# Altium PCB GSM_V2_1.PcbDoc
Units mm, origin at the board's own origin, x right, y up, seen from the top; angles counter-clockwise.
Board outline 86 x 46.6 mm, 2 copper layers (Top Layer, Bottom Layer); 76 components, 54 nets, 270 pads, 34 vias.
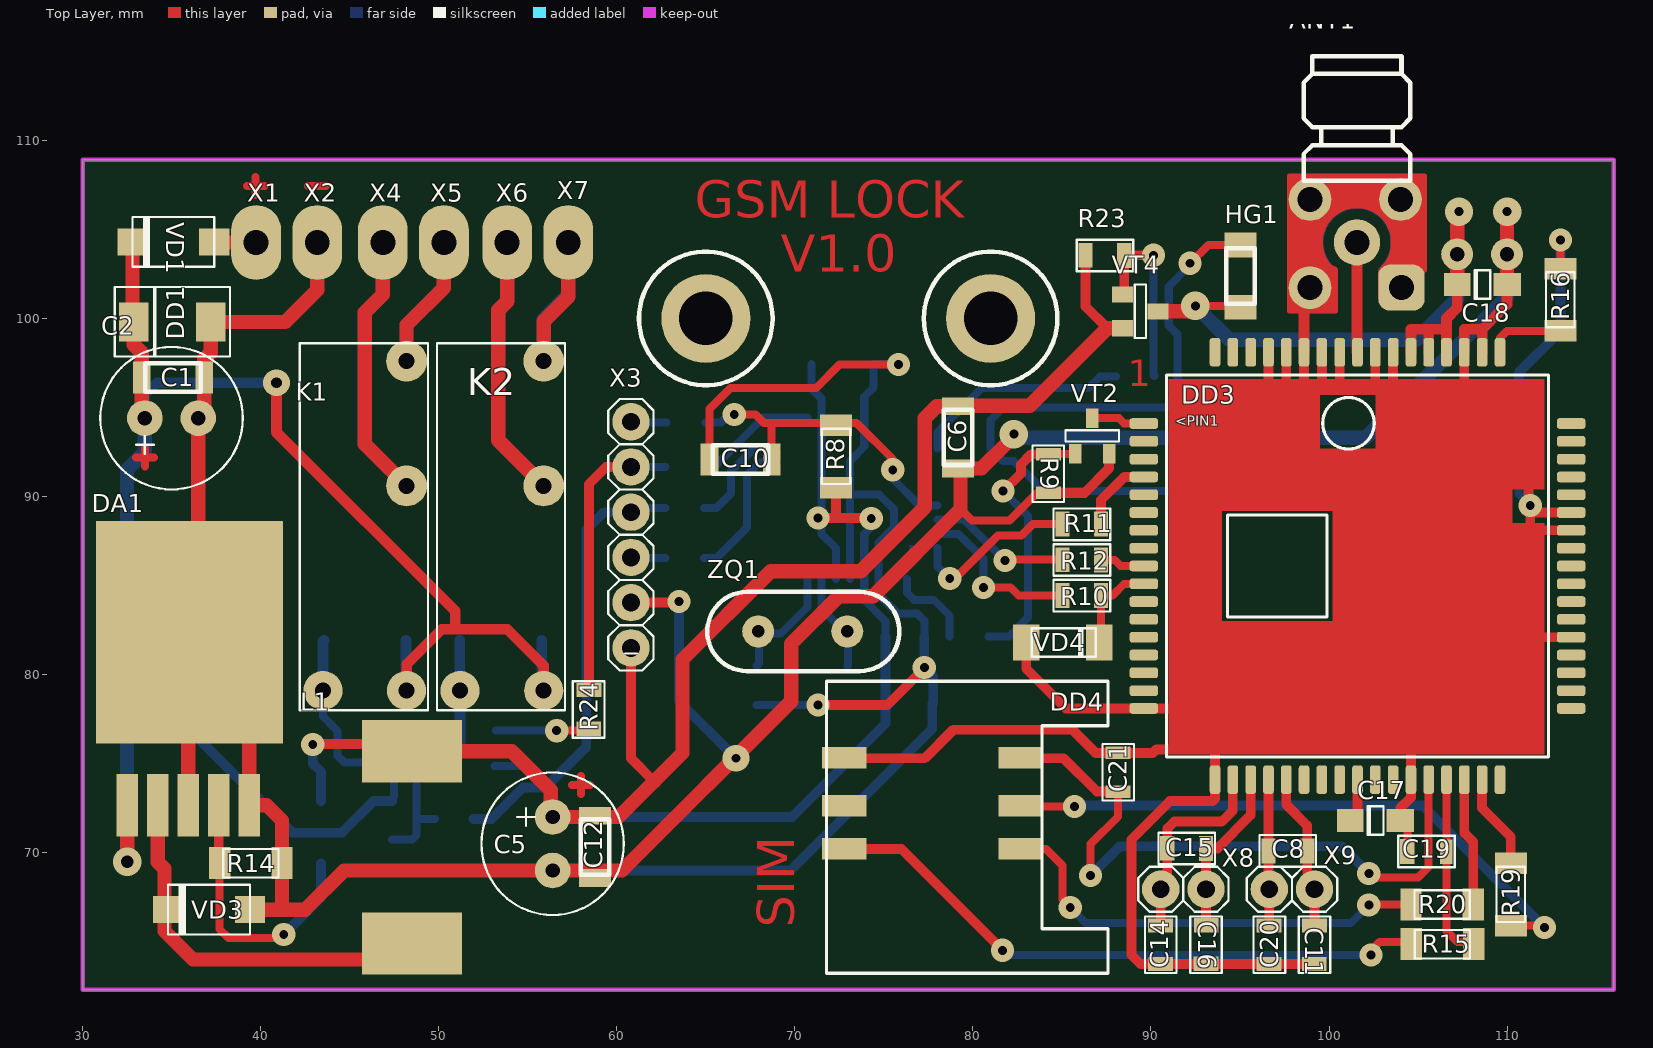
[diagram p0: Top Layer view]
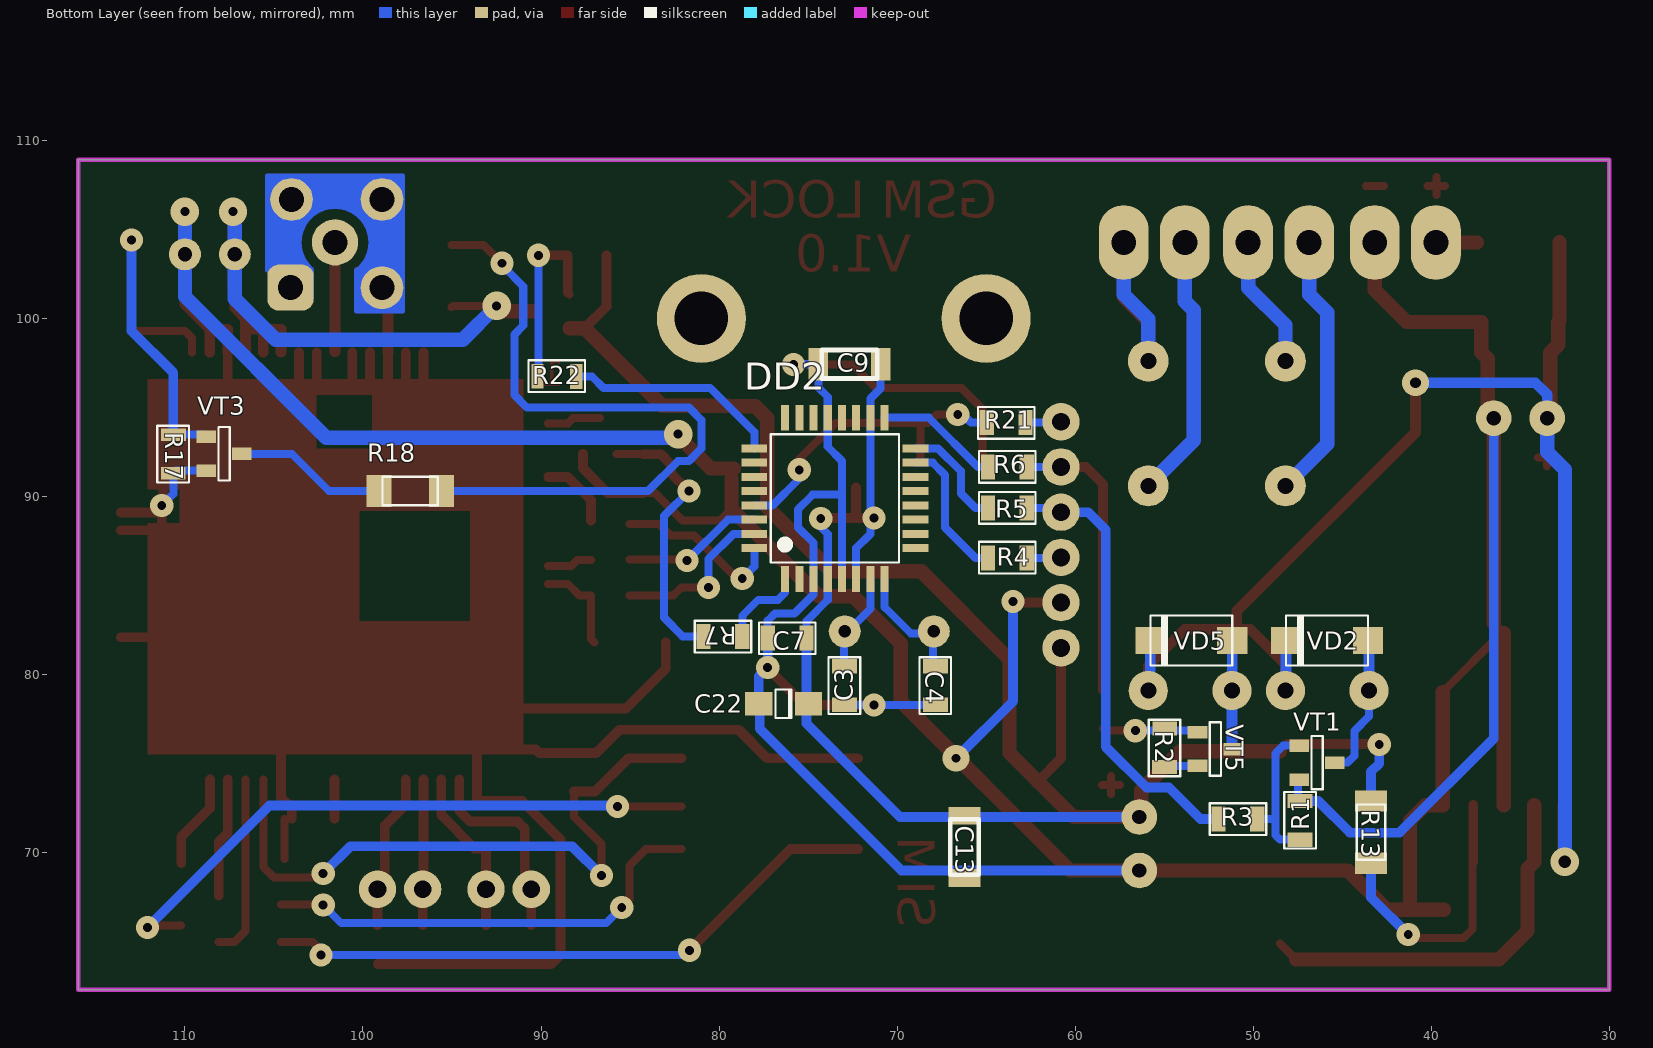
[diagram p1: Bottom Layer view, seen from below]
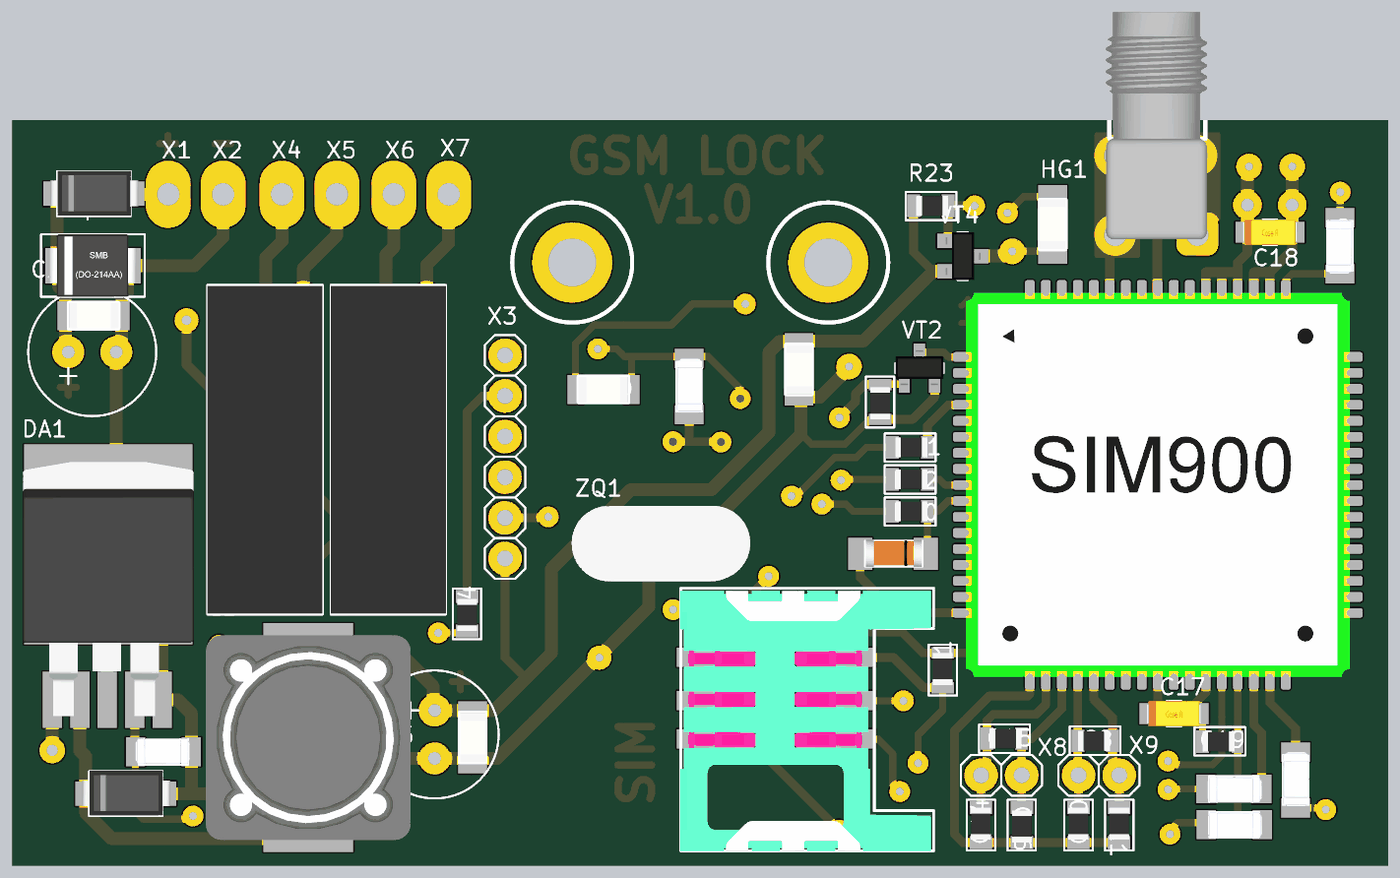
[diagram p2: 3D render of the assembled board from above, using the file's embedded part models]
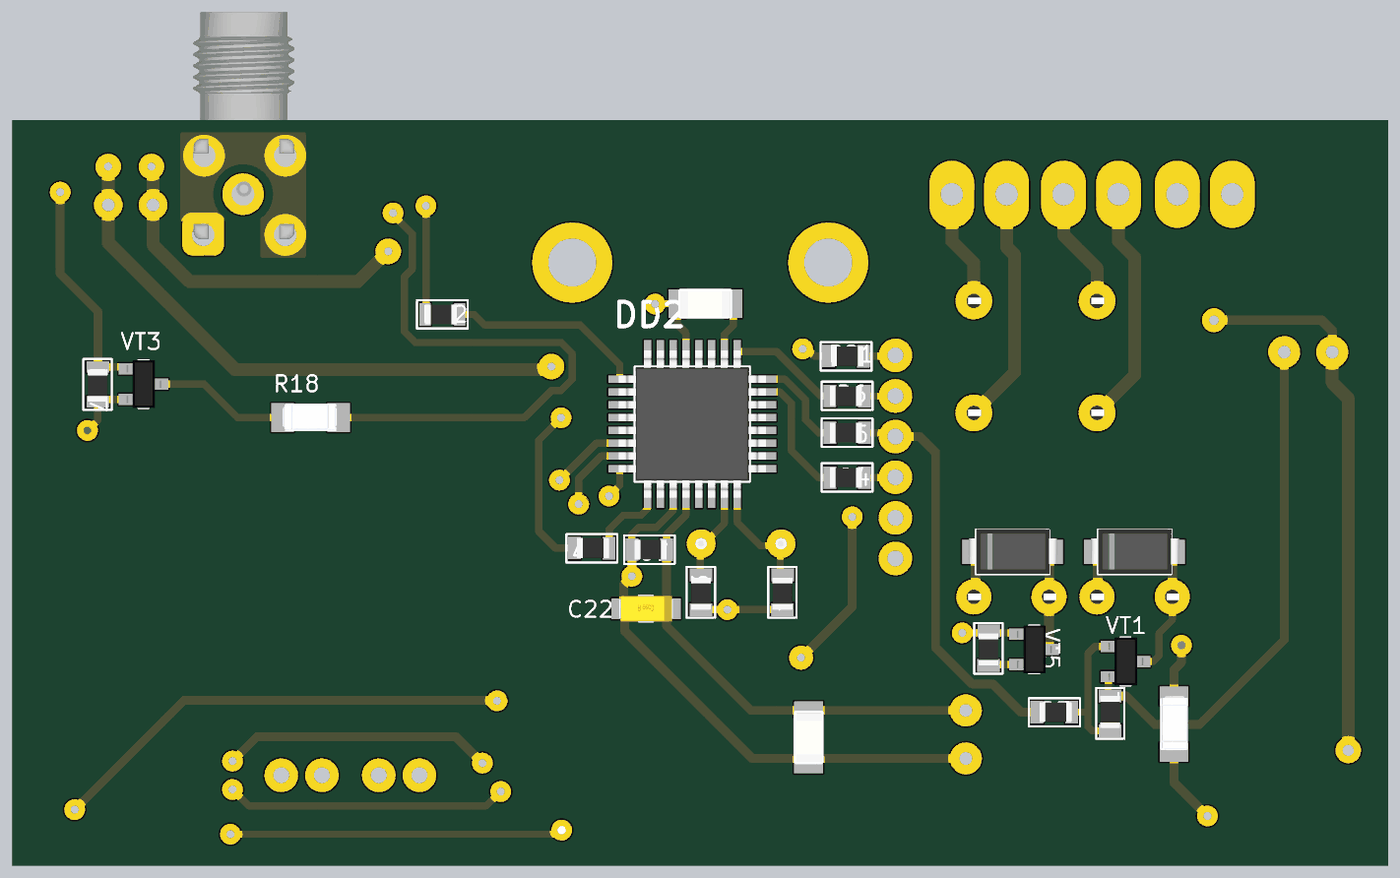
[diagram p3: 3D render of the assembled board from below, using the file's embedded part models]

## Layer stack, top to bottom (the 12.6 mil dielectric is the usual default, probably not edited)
Top Solder: solder mask 0.0102, Solder Resist, Dk 3.5
Top Layer: signal copper 0.0356
Dielectric 1: dielectric 0.32, FR-4, Dk 4.8
Bottom Layer: signal copper 0.0356
Bottom Solder: solder mask 0.0102, Solder Resist, Dk 3.5

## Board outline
30,62.3 116,62.3 116,108.9 30,108.9

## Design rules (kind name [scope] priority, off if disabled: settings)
Clearance [All] p1: gap=0.23
PolygonConnect [All] p1: connectstyle=Relief reliefconductorwidth=0.254 reliefentries=4 polygonreliefangle="90 Angle" airgapwidth=0.254
RoutingVias [All] p1: holewidth=0.711 width=1.27 viastyle="Through Hole" minholewidth=0.711 minwidth=1.27 maxholewidth=0.711 maxwidth=1.27
SMDNeckDown [All] p1: percent=100.000
SolderMaskExpansion [All] p1: expansion=0.102
Width [All] p1: maxlimit=0.8 minlimit=0.45 preferedwidth=0.6
29 further rules are at their usual default settings.

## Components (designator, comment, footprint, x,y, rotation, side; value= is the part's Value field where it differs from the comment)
ANT1 "ANT" ANTENNA 101.6,104.3 r0 top
C1 "100nF" 1206_CAP#1 33.2,97.3 r0 top
C2 "470uF" 3mm 36.5,94.4 r180 top
C3 "18" 0805#1 73.6,78.3 r90 bottom
C4 "18" 0805#1 68.5,78.3 r90 bottom
C5 "1000uF" 3mm 56.4,69 r90 top
C6 "100nF" 1206_CAP#1 79.8,95.2 r270 top
C7 "100nF" 0805#1 75.1,81.407 r0 bottom
C8 "10" 0805#1 96.6,70.739 r0 top
C9 "100nF" 1206_CAP#2 70.8,96.8 r0 bottom
C10 "100nF" 1206_CAP#1 68.834,91.44 r180 top
C11 "10" 0805#1 99.822,65.913 r270 top
C12 "100nF" 1206_CAP#1 59.4,72.2 r270 top
C13 "100nF" 1206_CAP#1 65.6,72.2 r270 bottom
C14 "10" 0805#1 91.186,65.913 r270 top
C15 "10" 0805#1 93.091,69.596 r180 top
C16 "10" 0805#1 92.456,63.754 r90 top
C17 "4.7uF" A 104.2,71.8 r180 top
C18 "10uF" A 110.2,101.9 r180 top
C19 "10" 0805#2 104.4,70.7 r0 top
C20 "10" 0805#1 97.282,65.913 r270 top
C21 "100nF" 0805#3 88.8,75.6 r270 top
C22 "10uF" A 77.978,78.359 r180 bottom
DA1 "LM2576S-ADJ" D2PAK-5 36,83.4 r270 top
DD1 "SMBJ15A" SMB(DO-214AA) 37.2,99.8 r180 top
DD2 "Atmega8A-AU" TQFP32 76.3,85.5 r90 bottom
DD3 "SIM900R" SIM900 89.6,98.1 r0 top
DD4 "SIM_card" 6393699-1 71.882,79.629 r0 top
HG1 "LED_3mm" 1206_CAP#3 94.4,100.5 r90 top
K1 "G5NB-1A-E" G5NB-1A-E 43.5,79.1 r90 top
K2 "G5NB-1A-E" G5NB-1A-E 51.2,79.1 r90 top
L1 "100uH" B82477G4 48.5,65.1 r90 top
R1 "4.7k" 0805#1 46.736,72.898 r270 bottom
R2 "4.7k" 0805#1 55.626,74.803 r90 bottom
R3 "4.7k" 0805#1 49.784,71.247 r0 bottom
R4 "200" 0805#1 64.9,87.2 r180 bottom
R5 "200" 0805#1 64.9,90 r180 bottom
R6 "200" 0805#1 64.9,92.3 r180 bottom
R7 "4.7k" 0805#1 78.7,81.5 r0 bottom
R8 "4.7k" 1206#1 72.4,90.4 r90 top
R9 "4.7k" 0805#3 83.6,90.2 r90 top
R10 "1k" 0805#1 87.2,83.8 r180 top
R11 "200" 0805#1 87.2,87.8 r180 top
R12 "1k" 0805#1 87.2,85.8 r180 top
R13 "2.2k" 1206#1 43.3,69.3 r90 bottom
R14 "1k" 1206#1 41.3,69.5 r180 top
R15 "22" 1206#1 104.521,64.77 r0 top
R16 "4.7k" 1206#1 112.9,102.9 r270 top
R17 "4.7k" 0805#3 111.3,91.3 r90 bottom
R18 "200" 1206#2 95.5,90.4 r0 bottom
R19 "22" 1206#1 110.3,65.8 r90 top
R20 "22" 1206#1 104.5,67 r0 top
R21 "200" 0805#1 62.8,93.5 r0 bottom
R22 "200" 0805#3 90.2,97.4 r180 bottom
R23 "4.7k" 0805#1 88.5,102.9 r180 top
R24 "4.7k" 0805#1 57.785,76.962 r90 top
VD1 "15MQ040N" SMA(DO-214AC) 37.4,104.3 r180 top
VD2 "S1M" SMA(DO-214AC) 43.561,81.915 r0 bottom
VD3 "15MQ040N" SMA(DO-214AC) 39.4,66.8 r180 top
VD4 "2V7" SOD80 83.3,81.8 r0 top
VD5 "S1M" SMA(DO-214AC) 51.181,81.915 r0 bottom
VT1 "BC817-40" SOT23#1 45.72,75.057 r270 bottom
VT2 "BC817-40" SOT23#1 86.7,94.1 r0 top
VT3 "BC817-40" SOT23#1 107.1,92.4 r270 bottom
VT4 "IRLML2244" SOT23#2 90.1,100.4 r270 top
VT5 "BC817-40" SOT23#1 51.435,75.819 r270 bottom
X1 "CON1" ZL201-1G#1 39.751,104.267 r0 top
X2 "CON1" ZL201-1G#2 43.18,104.267 r90 top
X3 "PLC6" ZL201-6G 60.8,81.5 r180 top
X4 "CON1" ZL201-1G#1 46.863,104.267 r0 top
X5 "CON1" ZL201-1G#1 50.292,104.267 r0 top
X6 "CON1" ZL201-1G#1 53.848,104.267 r0 top
X7 "CON1" ZL201-1G#1 57.277,104.267 r0 top
X8 "микрофон" ZL201-2G 90.551,67.945 r90 top
X9 "Динамик" ZL201-2G 96.647,67.945 r90 top
ZQ1 "16Mhz" CRUSTAL 67.945,82.423 r0 top

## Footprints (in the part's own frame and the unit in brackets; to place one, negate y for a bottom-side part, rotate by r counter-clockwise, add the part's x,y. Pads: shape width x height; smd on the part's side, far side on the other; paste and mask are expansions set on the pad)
3mm [mm]
  round 2 hole 0.8: 1(0,0) 2(3,0)
  silkscreen extent -2.5,-4 5.5,4
0805#1 [mm]
  rect 0.8x1.4 smd: 1(0,-0.645) 2(2.173,-0.65)
  silkscreen extent -0.51,-1.52 2.67,0.25, body extent 0,-1.27 2,-0.02, height 0.5
0805#2 [mm]
  rect 0.8x1.4 smd: 1(0,-0.645)
  rect 0.7x1.4 smd: 2(2.173,-0.65)
  silkscreen extent -0.51,-1.52 2.67,0.25, body extent 0,-1.27 2,-0.02, height 0.5
0805#3 [mm]
  rect 0.7x1.4 smd: 1(0,-0.645) 2(2.173,-0.65)
  silkscreen extent -0.51,-1.52 2.67,0.25, body extent 0,-1.27 2,-0.02, height 0.5
1206#1 [mm]
  rect 1.2x1.8 smd: 1(0.101,0.089) 2(3.601,0.089)
  silkscreen extent 0.3,-0.71 3.4,0.89, body extent 0.21,-0.76 3.6,0.85, height 1.7
1206#2 [mm]
  rect 1.4x1.8 smd: 1(0.101,0.089) 2(3.601,0.089)
  silkscreen extent 0.3,-0.71 3.4,0.89, body extent 0.21,-0.76 3.61,0.85, height 1.7
1206_CAP#1 [mm]
  rect 1x1.8 smd: 1(0.13,-0.628) 2(3.63,-0.628)
  silkscreen extent 0.33,-1.43 3.43,0.17, body extent 0.35,-1.4 3.45,0.2, height 1
1206_CAP#2 [mm]
  rect 1.1x1.8 smd: 1(0.13,-0.628) 2(3.63,-0.628)
  silkscreen extent 0.33,-1.43 3.43,0.17, body extent 0.35,-1.4 3.45,0.2, height 1
1206_CAP#3 [mm]
  rect 1.4x1.8 smd: 1(0.13,-0.628) 2(3.63,-0.628)
  silkscreen extent 0.33,-1.43 3.43,0.17, body extent 0.35,-1.4 3.45,0.2, height 1
6393699-1 [mm]
  rect 2.5x1.2 smd: 1(0.9,-4.3) 2(0.9,-7) 3(0.9,-9.4) 4(10.8,-9.4) 5(10.8,-7) 6(10.8,-4.3)
  silkscreen extent -0.1,-16.4 15.7,0, body extent -0.12,-16.45 15.53,-0.15, height 2.7
A [mm]
  rect 1.55x1.3 smd: 1(0.2,0)
  rect 1.5x1.3 smd: 2(3,0)
  silkscreen extent 1.14,-0.8 2.03,0.8, body extent -0.1,-0.8 3.29,0.8, height 1.65
ANTENNA [mm]
  round 2.6 hole 1.4: 1(-0.029,-0.026)
  rrect50% 2.6x2.6 hole 1.4: 2(2.471,-2.566)
  Top Layer circle w0.254: c-2.629,-2.586 r0.4
  Top Layer circle w0.254: c-2.629,2.414 r0.4
  Top Layer circle w0.254: c2.471,2.414 r0.4
  Top Layer region: -1.729,3.614 -2.029,3.614 -2.929,2.914 -2.229,2.714
  Top Layer region: 2.771,3.614 2.571,3.614 2.571,2.914 2.771,2.714
  Top Layer region: -2.929,-2.286 -2.629,-2.086 -3.729,-1.486 -3.729,-1.886
  Top Layer region: 1.171,-1.586 1.171,-3.186 1.571,-3.786 1.471,-1.386
  Top Layer region: 1.971,2.314 2.271,2.714 2.471,2.914 2.671,2.814 2.571,3.614 1.671,3.614 -1.829,3.614 -2.529,2.914 -2.229,2.414 -2.329,2.114 -2.629,2.014 -2.929,2.214 -2.929,2.514 -2.829,2.714 -1.929,3.614 -3.729,3.614 -3.729,1.574 -3.729,-1.726 -2.229,-2.386 -2.229,-2.686 -2.329,-2.886 -2.629,-3.086 -2.929,-2.786 -2.929,-2.486 -2.829,-2.186 -3.729,-1.786 -3.729,-3.786 -1.129,-3.786 -1.129,-1.486 -1.229,-1.386 -1.629,-1.226 -1.929,-0.726 -2.029,-0.126 -1.929,0.474 -1.829,0.814 -1.629,1.174 -1.329,1.514 -0.829,1.774 -0.429,1.874 0.171,1.974 0.971,1.674 1.471,1.314 1.871,0.414 1.871,-0.626 1.271,-1.826 3.671,-1.826 3.671,1.674 3.671,3.614 2.671,3.614 2.771,2.814 2.871,2.114 2.471,1.914
  Top Layer lines w0.254: -1.418,-1.52 cw(c-0.029,-0.026) 1.362,-1.518 ; -1.229,-1.586 -1.229,-3.886 -3,-3.886 -3.829,-3.886 -3.829,3.714 3.771,3.714 3.771,-1.586
  Bottom Layer circle w0.254: c-2.629,-2.586 r0.4
  Bottom Layer circle w0.254: c-2.629,2.414 r0.4
  Bottom Layer circle w0.254: c2.471,2.414 r0.4
  Bottom Layer region: -2.529,-1.986 -2.329,-2.186 -2.129,-2.586 -2.029,-2.986 -1.129,-2.886 -1.129,-1.586 -1.329,-1.486
  Bottom Layer region: -1.129,-1.686 -1.129,-1.486 -1.329,-1.386
  Bottom Layer region: 2.071,-1.786 3.671,-1.686 3.671,2.114 1.171,1.514 1.471,1.214 1.871,0.514 1.971,-0.186 1.771,-0.686 1.571,-1.186 1.171,-1.586 1.171,-3.186
  Bottom Layer region: 3.671,2.114 3.671,3.614 1.471,3.614
  Bottom Layer region: 2.871,2.914 2.771,2.014 2.071,2.014 2.071,1.514 3.671,1.714 3.671,2.414
  Bottom Layer region: 2.071,2.614 2.571,3.014 1.471,3.614 -2.329,3.614 -2.329,2.914 -2.229,2.314 -1.829,0.914 -1.329,1.614 -0.629,1.914 0.571,1.914 1.271,1.514 2.171,1.714
  Bottom Layer region: -2.329,3.614 -3.729,3.614 -3.729,-3.786 -1.129,-3.786 -1.129,-2.786 -2.129,-2.586 -2.329,-2.986 -2.629,-3.086 -2.829,-2.886 -2.929,-2.586 -2.929,-2.386 -2.729,-2.286 -2.429,-2.186 -1.329,-1.586 -1.829,-0.986 -2.129,0.014 -1.929,0.714 -1.729,1.214 -2.129,2.214 -2.429,2.014 -2.629,2.114 -2.829,2.114 -2.929,2.314 -2.929,2.514 -2.829,2.714 -2.529,2.814 -2.029,2.714
  Bottom Layer lines w0.254: -1.346,-1.531 cw(c-0.029,-0.026) 1.288,-1.531 ; -1.229,-1.586 -1.229,-3.886 -3.829,-3.886 -3.829,3.714 3.771,3.714 3.771,-1.586
  silkscreen extent -3.03,3.43 2.97,10.43, body extent -3.25,-2.85 3.09,11.35, height 10.48
B82477G4 [mm]
  rect 3.5x5.6 smd: 1(-0.2,0) 2(10.6,0)
  body extent -1.2,-6.4 11.6,6.4, height 8
CRUSTAL [mm]
  round 1.8 hole 0.7: 1(0,0) 2(5,0)
  silkscreen extent -2.85,-2.22 7.93,2.22, body extent -2.99,-2.3 8.19,2.37, height 3.83
D2PAK-5 [mm]
  rect 3.5x1.2 smd: 1(10.731,-3.492) 2(10.731,-1.778) 3(10.731,-0.063) 4(10.731,1.651) 5(10.731,3.366)
  rect 12.5x10.5 smd: 3(1.016,0)
  body extent -4.13,-5.33 11.75,5.34, height 4.83
G5NB-1A-E [mm]
  round 2.2 hole 0.9: 1(0,-4.7) 4(0,0)
  round 2.3 hole 0.9: 2(11.5,-4.7) 3(18.5,-4.7)
  silkscreen extent -1.1,-5.9 19.5,1.3, body extent -1.05,-5.9 19.45,1.3, height 15.3
SIM900 [mm]
  rrect50% 1.6x0.6 smd: 1(0,-4) 2(0,-5) 3(0,-6) 4(0,-7) 5(0,-8) 6(0,-9) 7(0,-10) 8(0,-11) 9(0,-12) 10(0,-13) 11(0,-14) 12(0,-15) 13(0,-16) 14(0,-17) 15(0,-18) 16(0,-19) 17(0,-20) 35(24,-20) 36(24,-19) 37(24,-18) 38(24,-17) 39(24,-16) 40(24,-15) 41(24,-14) 42(24,-13) 43(24,-12) 44(24,-11) 45(24,-10) 46(24,-9) 47(24,-8) 48(24,-7) 49(24,-6) 50(24,-5) 51(24,-4)
  rrect50% 0.6x1.6 smd: 18(4,-24) 19(5,-24) 20(6,-24) 21(7,-24) 22(8,-24) 23(9,-24) 24(10,-24) 25(11,-24) 26(12,-24) 27(13,-24) 28(14,-24) 29(15,-24) 30(16,-24) 31(17,-24) 32(18,-24) 33(19,-24) 34(20,-24) 52(20,0) 53(19,0) 54(18,0) 55(17,0) 56(16,0) 57(15,0) 58(14,0) 59(13,0) 60(12,0) 61(11,0) 62(10,0) 63(9,0) 64(8,0) 65(7,0) 66(6,0) 67(5,0) 68(4,0)
  silkscreen extent 1.27,-22.73 22.73,-1.27, body extent 0,-24 24,0, height 3
SMA(DO-214AC) [mm]
  rect 1.7x1.524 smd: 1(0,0) 2(4.6,0)
  silkscreen extent 0,-1.4 4.6,1.4, body extent -0.48,-1.43 5.02,1.37, height 2.31
SMB(DO-214AA) [mm]
  rect 1.65x2.2 smd: 1(0,0) 2(4.318,0)
  silkscreen extent -1.08,-1.96 5.4,1.94, body extent -0.57,-1.96 4.93,1.94, height 2.45
SOD80 [mm]
  rect 1.5x2 smd: 1(-0.3,0) 2(3.8,0)
  silkscreen extent 0,-0.8 3.6,0.8, body extent 0.05,-0.82 3.55,0.88, height 1.7
SOT23#1 [mm]
  rect 0.7x1.1 smd: 1(-0.95,-1.7) 2(0.95,-1.7) 3(0,0.3)
  silkscreen extent -1.5,-1.02 1.5,-0.38, body extent -1.5,-2 1.5,0.65, height 1.2
SOT23#2 [mm]
  rect 0.9x1.2 smd: 1(-0.95,-1.7) 2(0.95,-1.7) 3(0,0.3)
  silkscreen extent -1.5,-1.02 1.5,-0.38, body extent -1.5,-2 1.5,0.65, height 1.2
TQFP32 [mm]
  rect 1.45x0.45 smd: 1(-0.127,0) 2(-0.127,-0.8) 3(-0.127,-1.6) 4(-0.127,-2.4) 5(-0.127,-3.2) 6(-0.127,-4) 7(-0.127,-4.8) 8(-0.127,-5.6) 17(8.927,-5.6) 18(8.927,-4.8) 19(8.927,-4) 20(8.927,-3.2) 21(8.927,-2.4) 22(8.927,-1.6) 23(8.927,-0.8) 24(8.927,0)
  rect 0.45x1.45 smd: 9(1.6,-7.327) 10(2.4,-7.327) 11(3.2,-7.327) 12(4,-7.327) 13(4.8,-7.327) 14(5.6,-7.327) 15(6.4,-7.327) 16(7.2,-7.327) 25(7.2,1.727) 26(6.4,1.727) 27(5.6,1.727) 28(4.8,1.727) 29(4,1.727) 30(3.2,1.727) 31(2.4,1.727) 32(1.6,1.727)
  silkscreen extent 0.8,-6.4 8,0.8, body extent -0.2,-7.4 9,1.8, height 1.2
ZL201-1G#1 [mm]
  oval 2.8x4.2 hole 1.4: 1(0,0)
ZL201-1G#2 [mm]
  oval 4.2x2.8 hole 1.4: 1(0,0)
ZL201-2G [mm]
  round 2.1 hole 1: 1(0,0) 2(0,-2.54)
  silkscreen extent -1.27,-3.81 1.27,1.27, body extent -1.27,-3.81 1.27,1.27, height 8.54
ZL201-6G [mm]
  round 2.1 hole 1: 1(0,0) 2(0,-2.54) 3(0,-5.08) 4(0,-7.62) 5(0,-10.16) 6(0,-12.7)
  silkscreen extent -1.27,-13.97 1.27,1.27, body extent -1.27,-13.97 1.27,1.27, height 8.54

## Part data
C1 C3 C4 C6 C7 C8 C9 C10 C11 C12 C13 C14 C15 C16 C19 C20 C21: library part CAP
C2 C5: library part CAP_POL
C17 C18 C22: library part tantalum
DA1: library part LM2576-ADJ, "Step-Down  Switching Regulator"
DD1: "Защитный диод"
DD2: "8 KB Flash, 8-chennel ADC"
DD3: "GSM/GPRS"
K1 K2: "РЕЛЕ"
L1: library part INDUCTOR
R1 R2 R3 R4 R5 R6 R7 R8 R9 R10 R11 R12 R13 R14 R15 R16 R17 R18 R19 R20 R21 R22 R23 R24: library part res_0.125
VD1 VD2 VD5: library part 1N4007
VD4: library part "ZENER DIOD"
VT1 VT2 VT3 VT5: library part BC817, "N-P-N"
VT4: "P-Channel  -20 V -4.3A"
X8 X9: library part PLC2
ZQ1: library part CRYSTAL

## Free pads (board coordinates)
  round 5 hole 3 unplated: 0(65,100) 1(81,100)
  round 1.8 hole 0.8: 0(107.2,103.6) 1(110,103.6)
  round 2.4 hole 1.4: 2(98.933,101.727) 3(98.933,106.68) 4(104.013,106.68)

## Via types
v1: diameter 1.3, hole 0.5, Top Layer to Bottom Layer, 27 vias
v2: diameter 1.6, hole 0.5, Top Layer to Bottom Layer, 4 vias
v3: diameter 1.5, hole 0.6, Top Layer to Bottom Layer, 1 vias
v4: diameter 1.5, hole 0.5, Top Layer to Bottom Layer, 1 vias
v5: diameter 1.6, hole 0.7, Top Layer to Bottom Layer, 1 vias

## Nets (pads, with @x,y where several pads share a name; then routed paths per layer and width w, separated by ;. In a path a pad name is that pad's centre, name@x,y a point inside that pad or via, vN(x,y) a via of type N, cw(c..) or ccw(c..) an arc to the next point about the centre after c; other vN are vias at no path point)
+4V: C5.2 C6.1 C7.1 C9.1 C12.1 C13.1 C22.2 DD2.4 DD2.6 DD2.18 L1.2 R8.1 R13.2 R23.2 VT4.2 X3.1 | length 130.9
  Top Layer w0.45: L1.2@48.1,76.1 L1.2 ; 72.3,88.8 72.311,88.811 ; C6.1@79.172,94.772 C6.1@79.5,95.1
  Top Layer w0.55: v1@43.4,76.1 L1.2@48.1,76.1 ; X3.1 60.8,75.3 62.1,74 ; v1(71.3,88.8) 72.3,88.8 v1@74.295,88.8 ; 72.311,88.811 R8.1 ; R23.2 86.327,100.673 87.55,99.45
  Top Layer w0.8: L1.2 54.1,75.7 56.3,73.5 56.3,72 60.1,72 62.1,74 63.7,75.6 63.7,80.845 68.655,85.8 73.7,85.8 77.3,89.4 77.3,94.4 77.97,95.07 C6.1 ; C6.1@79.5,95.1 83.2,95.1 87.55,99.45 VT4.2
  Bottom Layer w0.45: C9.1 70.93,96.07 71.5,95.5 DD2.18 71.5,87.9 72.3,87.1 DD2.6 ; v1@74.295,88.295 73.9,87.9 DD2.4 73.9,84.2 75.1,83 C7.1@75.1,82.145
  Bottom Layer w0.55: v1(42.926,76.073) 42.926,75.012 43.389,74.549 R13.2 ; C5.2@56.5,72 69.841,72 75.1,77.259 C7.1@75.1,82.145
  other v1: 74.295,88.773
+12V: C1.1 C2.2 DA1.1 DD1.2 K1.1 K2.1 VD1.2 VD2.2 VD5.2 | length 83.4
  Top Layer w0.45: DD1.2@32.8,99.882 DD1.2 ; C2.2@33.33,94.57 C2.2
  Top Layer w0.6: v3(40.894,96.393) 40.894,93.599 50.927,83.566 50.927,82.55 ; K1.1 48.2,80.585 50.165,82.55 50.927,82.55 ; K2.1 55.9,80.498 53.848,82.55 50.927,82.55
  Top Layer w0.8: v5@32.507,69.707 DA1.1 ; DD1.2@32.8,99.882 VD1.2 ; DD1.2 32.882,98.518 33.33,98.07 C1.1 C2.2@33.33,94.57
  Bottom Layer w0.6: C2.2 33.5,95.73 34.163,96.393 v3(40.894,96.393) ; VD2.2 48.161,79.139 K1.1 ; VD5.2 55.781,79.219 K2.1
  Bottom Layer w0.8: v5(32.5,69.5) 32.5,91.5 33.5,92.5 C2.2
GND: ANT1.2 C1.2 C2.1 C3.1 C4.1 C5.1 C6.2 C7.2 C9.2 C10.2 C11.2 C12.2 C13.2 C14.2 C16.1 C17.1 C18.1 C19.1 C20.2 C21.1 C22.1 DA1.3 DA1.5 DD1.1 DD2.3 DD2.5 DD2.21 DD3.17 DD3.18 DD3.29 DD3.39 DD3.45 DD3.46 DD3.53 DD3.54 DD3.58 DD3.59 DD3.61 DD3.62 DD3.63 DD3.64 DD3.65 DD4.1 pad.1@110,103.6 pad.2 pad.3 pad.4 R1.1 R9.1 R14.1 R17.1 VD3.1 VD4.1 VT1.2 VT2.2 VT3.2 X2.1 X3.2 | length 443.4
  Top Layer w0.45: DA1.3@35.936,82.321 DA1.3@36,82.384 ; DA1.3@36.5,82.884 DA1.3@36,82.384 ; C2.1 C2.1@36.83,94.73 ; DA1.3@39.365,79.019 DA1.3@36,82.384 ; v1@63.44,84.04 v1(63.5,84.1) ; C10.2 65.204,94.922 66.382,96.1 71.2,96.1 72.509,97.409 v1(75.819,97.409) ; v1@77.3,80.4 v1@77.3,80.5 ; 79.3,89.3 79.954,88.646 82.051,88.646 83.605,90.2 R9.1 ; 91.2,78.1 91.2,75.8 93.6,75.8 104.6,75.8 111.6,75.8 111.6,82.1 111.6,88.1 ; 96.6,96.2 100.6,96.2 ; pad.2@98.5,101.4 98.6,101.3 98.6,100.414 ; 100.6,96.1 102.6,96.1 ; 102.6,96.2 107.6,96.2 111.2,96.2 ; C19.1@104.4,69.655 C17.1@104.4,71.9
  Top Layer w0.55: X3.2 v1@63.44,84.04 ; v1(71.3,78.3) 75.2,78.3 v1@77.3,80.4 ; DD4.1@72.2,75.3 77.3,75.3 78.9,76.9 85.6,76.9 86.9,75.6 C21.1 90.1,75.6 90.3,75.8 91.2,75.8 ; VD4.1 83,80.322 85.222,78.1 DD3.17 91.2,78.1 ; R9.1 86.263,90.2 87.65,91.587 VT2.2 ; 93.6,75.8 DD3.18 93.6,73.026 93.472,72.898 91.059,72.898 88.9,70.739 88.9,64.262 89.422,63.74 C14.2 C20.2 C11.2 ; 96.6,96.2 DD3.65 ; 97.6,96.6 DD3.64 ; 98.6,96.55 DD3.63 ; 99.6,96.5 DD3.62 ; 100.6,96.2 DD3.61 ; 102.6,96.2 DD3.59 ; 103.6,96.5 DD3.58 ; C17.1@104,71.9 104,72.5 104.6,73.1 DD3.29 104.6,75.8 ; 107.6,96.2 DD3.54 ; v1@111.2,89.8 111.2,96.2 ; 111.6,82.1 DD3.39 ; DD3.45 111.3,88.1 111.3,89.1 DD3.46
  Top Layer w0.6: DD3.63 98.6,100.414 ; DD3.54 107.6,99.4 108.6,99.4 ; DD3.53 108.6,99.4 ; C18.1 110,100.8 108.6,99.4
  Top Layer w0.8: DA1.3@35.936,72.669 DA1.3@35.936,82.321 ; DA1.3@36.5,82.884 C2.1 ; C2.1@36.83,94.73 C1.2 36.83,97.73 37.2,98.1 DD1.1 41.38,99.8 43.18,101.6 X2.1 ; VD3.1@39.3,66.8 41.199,66.8 ; DA1.3@39.365,79.019 DA1.5 40.331,72.669 41.199,71.801 R14.1 41.199,66.8 ; C6.2 80.47,91.57 v2@81.8,92.9 ; 79.3,91 79.3,89.3 74.4,84.4 72.462,84.4 69.8,81.738 69.8,78.5 60.3,69 44.7,69 42.5,66.8 41.199,66.8 ; C18.1 v2@110,105.2
  Bottom Layer w0.45: R1.1@47.498,73.152 VT1.2@47.498,74.107 ; C4.1 v1(71.3,78.3) C3.1 ; DD2.5 73.1,90.1 ; v1(75.819,97.409) 75.8,97.428 C9.2 74.43,96.13 73.9,95.6 DD2.21 73.9,92.8 73.1,92 73.1,90.1 ; C7.2@77.273,82.15 77.273,83.027 76.861,83.439 75.761,83.439 74.7,84.5 DD2.3 74.7,87.4 75.565,88.265 75.565,89.281 74.746,90.1 73.1,90.1 ; VT3.2 110.505,91.45 R17.1 110.655,90.145 v1(111.3,89.5)
  Bottom Layer w0.55: C2.1 36.5,76.403 41.783,71.12 44.577,71.12 46.355,72.898 R1.1 ; C5.1@56.5,69 69.762,69 77.724,76.962 C22.1@77.724,78.359 ; v1(63.5,84.1) 63.5,78.5 v4(66.7,75.3) ; C7.2@77.273,82.15 C7.2 v1(77.273,80.391) 77.778,79.886 C22.1
  Bottom Layer w0.8: v2@82.3,93.3 102.063,93.3 110,101.237 v2(110,106)
  other v2: 82.3,93.5
NetANT1_1: ANT1.1 DD3.60 | length 6.1
  Top Layer w0.6: DD3.60@101.571,98.129 ANT1.1
NetC3_2: C3.2 DD2.7 ZQ1.2 | length 5.5
  Bottom Layer w0.45: DD2.7 71.5,83.7 73,82.2 73,80.523 C3.2
NetC4_2: C4.2 DD2.8 ZQ1.1 | length 6.8
  Bottom Layer w0.45: C4.2 68,80.623 68,82.296 69.215,82.296 70.7,83.781 DD2.8
NetC8_1: C8.1 C20.1 DD3.21 X9.1 | length 8.2
  Top Layer w0.45: X9.1@96.6,67.992 X9.1 ; C20.1 C20.1@96.647,65.923
  Top Layer w0.55: X9.1@96.6,67.992 C8.1 DD3.21 ; C20.1@96.647,65.923 X9.1
NetC8_2: C8.2 C11.1 DD3.22 X9.2 | length 8.3
  Top Layer w0.45: X9.2@98.773,68.359 X9.2@98.806,68.326 ; C11.1 C11.1@99.187,65.923
  Top Layer w0.55: DD3.22 97.6,72.707 98.773,71.534 C8.2 X9.2@98.773,68.359 ; C11.1@99.187,65.923 X9.2
NetC10_1: C10.1 DD2.29 R8.2 R21.2 | length 18.4
  Top Layer w0.45: v1@66.3,94.6 67.8,94.6 68.27,94.13 68.58,94.13 ; C10.1 68.704,94.006 68.58,94.13 ; v1(75.5,91.5) 75.5,92.1 73.47,94.13 68.58,94.13
  Bottom Layer w0.45: R21.2 65.85,94.15 66.3,94.6 v1(66.6,94.6) ; v1(75.5,91.5) 75.5,91 77,89.5 DD2.29
NetC14_1: C14.1 C15.2 DD3.19 X8.1 | length 11.4
  Top Layer w0.45: C14.1 C14.1@90.551,65.923 ; X8.1 X8.1@90.918,68.312
  Top Layer w0.55: C14.1@90.551,65.923 X8.1 ; X8.1@90.918,68.312 C15.2 90.918,71.36 91.313,71.755 93.98,71.755 94.6,72.375 DD3.19
NetC15_1: C15.1 C16.2 DD3.20 X8.2 | length 9.6
  Top Layer w0.45: C16.2@93.091,65.942 C16.2
  Top Layer w0.55: C16.2@93.091,65.942 X8.2 C15.1 93.736,70.241 95.6,72.105 DD3.20
NetC17_2: C17.2 DD3.26 | length 2.2
  Top Layer w0.55: C17.2@101.6,71.9 DD3.26
NetC18_2: C18.2 DD3.55 DD3.56 DD3.57 HG1.1 pad.0@107.2,103.6 VT4.3 | length 38.1
  Top Layer w0.45: v2@92.2,100.4 v2(92.5,100.7) 94.958,100.7 HG1.1
  Top Layer w0.6: DD3.57 104.6,99.4 105.6,99.4 ; DD3.56 105.6,99.4 ; DD3.55 106.6,100 107.2,100.6 C18.2 ; 106.6,99.4 105.6,99.4
  Top Layer w0.8: VT4.3 v2@92.2,100.4 ; C18.2 v2@107.2,106
  Bottom Layer w0.8: v2(92.5,100.7) 94.4,98.8 104.896,98.8 107.2,101.104 107.2,105.2
  other v2: 107.3,106
NetC19_2: C19.2 DD3.31 R15.2 | length 10.3
  Top Layer w0.45: DD3.31 106.6,65.6 107.211,64.989 R15.2@108.101,64.989
NetC21_2: C21.2 DD3.30 DD4.6 | length 37.4
  Top Layer w0.45: v1(86.614,68.707) 86.614,70.485 88.15,72.021 C21.2 ; v1@102.489,68.6 105,68.6 105.6,69.2 DD3.30
  Top Layer w0.55: DD4.6@82.1,75.3 85.1,75.3 86.973,73.427 C21.2
  Bottom Layer w0.55: v1(86.614,68.707) 88.265,70.358 100.711,70.358 v1(102.235,68.834)
NetDA1_2: DA1.2 L1.1 VD3.2 | length 22.2
  Top Layer w0.45: L1.1@47.6,64 L1.1
  Top Layer w0.8: DA1.2 34.222,69.478 34.6,69.1 34.6,65.6 36.2,64 L1.1@47.6,64
NetDA1_4: DA1.4 R13.1 R14.2 | length 15.6
  Top Layer w0.45: R14.2@37.651,69.459 R14.2 37.699,65.701 38.2,65.2 v1@40.8,65.2
  Top Layer w0.55: R14.2@37.651,69.459 DA1.4
  Bottom Layer w0.45: v1@41,65.1 v1(41.3,65.4)
  Bottom Layer w0.55: v1(41.3,65.4) 43.389,67.489 R13.1
NetDD2_1: DD2.1 R7.1 | length 4.9
  Bottom Layer w0.45: DD2.1 76.3,84.6 76.699,84.201 77.799,84.201 78.7,83.3 R7.1
NetDD2_15: DD2.15 R4.1 | length 8
  Bottom Layer w0.45: R4.1 65.6,86.555 67.31,88.265 67.31,91.21 68,91.9 DD2.15
NetDD2_16: DD2.16 R5.1 | length 6.2
  Bottom Layer w0.45: R5.1 65.606,89.355 66.421,90.17 66.421,91.421 67.7,92.7 DD2.16
NetDD2_17: DD2.17 R6.1 | length 6.9
  Bottom Layer w0.45: R6.1 65.455,91.655 68.227,94.427 DD2.17
NetDD2_25: DD2.25 R22.2 | length 12.2
  Bottom Layer w0.45: DD2.25 78.027,93.627 80.5,96.1 86.5,96.1 87.15,96.75 R22.2
NetDD2_30: DD2.30 R12.2 | length 7.6
  Top Layer w0.45: v1@82.2,86.4 82.25,86.45 R12.2
  Bottom Layer w0.45: DD2.30 79.5,88.7 v1(81.8,86.4)
NetDD2_31: DD2.31 R10.2 | length 9.4
  Top Layer w0.45: v1(80.6,84.9) 82.105,84.9 82.555,84.45 R10.2
  Bottom Layer w0.45: DD2.31 79.2,87.9 80.6,86.5 v1(80.6,84.9)
NetDD2_32: DD2.32 R11.2 | length 9.6
  Top Layer w0.45: v1(78.7,85.4) 79,85.4 81.407,87.807 82.727,87.807 83.37,88.45 R11.2
  Bottom Layer w0.45: DD2.32 78.027,86.073 v1(78.7,85.4)
NetDD3_1: DD3.1 VT2.3 | length 3
  Top Layer w0.45: VT2.3 88.2,94.4 88.5,94.1 DD3.1
NetDD3_4: DD3.4 R11.1 | length 4.1
  Top Layer w0.55: R11.1@87.2,88.645 87.2,89.8 88.5,91.1 DD3.4
NetDD3_9: DD3.9 R12.1 | length 2.5
  Top Layer w0.45: R12.1 87.955,86.445 88.3,86.1 DD3.9
NetDD3_10: DD3.10 R10.1 VD4.2 | length 5.4
  Top Layer w0.45: VD4.2@87,81.8 87.2,82 R10.1 87.845,84.445 88.5,85.1 DD3.10
NetDD3_32: DD3.32 R20.2 | length 6.7
  Top Layer w0.55: DD3.32 107.6,71.1 108.101,70.599 R20.2@108.101,67.589
NetDD3_33: DD3.33 R19.2 | length 5.4
  Top Layer w0.55: DD3.33 108.6,72.5 110.211,70.889 R19.2
NetDD3_52: DD3.52 R16.2 | length 4.4
  Top Layer w0.45: DD3.52 109.6,98.9 109.999,99.299 R16.2
NetDD4_3: DD4.3 R15.1 | length 35.1
  Top Layer w0.45: v1@102.362,64.516 102.835,64.989 R15.1@104.601,64.989
  Top Layer w0.55: DD4.3@72.2,70.2 76,70.2 78.688,67.512 v1@81.672,64.528
  Bottom Layer w0.45: v1(81.661,64.516) 81.915,64.262 v1(102.362,64.262)
NetDD4_4: DD4.4 R20.1 | length 25.1
  Top Layer w0.45: DD4.4@82.1,70.2 84.105,70.2 85.026,69.278 v1@85.026,67.373 ; v1@102.268,67.089 R20.1
  Bottom Layer w0.45: v1(85.471,66.929) 86.36,66.04 101.219,66.04 v1(102.235,67.056)
NetDD4_5: DD4.5 R19.1 | length 34.6
  Top Layer w0.45: DD4.5@82.1,72.6 v1(85.7,72.6) ; R19.1 v1@112.1,65.901
  Bottom Layer w0.45: v1@86,72.3 v1@86.344,72.644
  Bottom Layer w0.55: v1@86.344,72.644 105.256,72.644 v1(112.1,65.8)
NetHG1_2: HG1.2 R18.1 | length 39.4
  Top Layer w0.45: v1(92.2,103.1) 93.23,104.13 HG1.2
  Bottom Layer w0.45: v1@92.1,102.9 91,101.8 91,99.6 91.5,99.1 91.5,95.7 90.8,95 81.7,95 81,94.3 81,92.7 81.7,92 82.3,92 83.989,90.311 R18.1
NetK1_2: K1.2 X4.1 | length 30.1
  Top Layer w0.8: X4.1 46.863,101.346 45.847,100.33 45.847,92.953 K1.2
  Bottom Layer w0.8: X4.1 46.863,101.346 45.847,100.33 45.847,92.953 K1.2
NetK1_3: K1.3 X5.1 | length 15.1
  Top Layer w0.8: K1.3 48.2,99.635 50.292,101.727 X5.1
  Bottom Layer w0.8: K1.3 48.2,99.635 50.292,101.727 X5.1
NetK1_4: K1.4 VD2.1 VT1.3 | length 8.3
  Bottom Layer w0.45: K1.4 43.5,77.658 44.323,76.835 44.323,75.438 44.704,75.057 VT1.3@45.593,75.057
  Bottom Layer w0.6: K1.4 43.5,81.854 VD2.1
NetK2_2: K2.2 X6.1 | length 29.9
  Top Layer w0.8: X6.1 53.848,100.965 53.34,100.457 53.34,93.16 K2.2
  Bottom Layer w0.8: X6.1 53.848,100.965 53.34,100.457 53.34,93.16 K2.2
NetK2_3: K2.3 X7.1 | length 14.5
  Top Layer w0.8: K2.3 55.9,99.842 57.277,101.219 X7.1
  Bottom Layer w0.8: K2.3 55.9,99.969 57.277,101.346 X7.1
NetK2_4: K2.4 VD5.1 VT5.3 | length 6.1
  Bottom Layer w0.6: VT5.3 51.2,75.884 K2.4 51.181,79.119 VD5.1
NetR1_2: R1.2 R3.1 VT1.1 | length 8.6
  Bottom Layer w0.45: R1.2 48.5,70.725 48.768,70.993 48.768,71.882 ; VT1.1 48.326,76.007 48.768,75.565 48.768,71.882 ; R3.1 48.778,71.892 48.768,71.882
NetR2_1: R2.1 VT5.2 | length 1.7
  Bottom Layer w0.45: VT5.2 R2.1@54.788,74.869
NetR2_2: R2.2 R24.1 VT5.1 | length 5.3
  Top Layer w0.45: v1(56.628,76.849) 58.317,76.849 R24.1
  Bottom Layer w0.45: VT5.1@53.215,76.849 54.976,76.849 v1(56.628,76.849) v1@56.642,76.835
NetR3_2: R3.2 R5.2 X3.4 | length 25.1
  Bottom Layer w0.45: X3.4 61.03,89.35 R5.2
  Bottom Layer w0.55: R3.2 52.974,71.897 54.737,73.66 56.007,73.66 58.293,75.946 58.293,88.138 59.275,89.12 X3.4
NetR4_2: R4.2 X3.3 | length 1.9
  Bottom Layer w0.45: X3.3 60.83,86.55 R4.2
NetR6_2: R6.2 R24.2 X3.5 | length 16.3
  Top Layer w0.55: R24.2 58.435,90.693 59.402,91.66 X3.5
  Bottom Layer w0.45: X3.5 60.81,91.65 R6.2
NetR7_2: R7.2 R9.2 VT2.1 | length 15.6
  Top Layer w0.45: R9.2 84.277,92.4 VT2.1
  Top Layer w0.55: v1(81.7,90.3) 82.7,91.3 82.7,91.8 83.273,92.373 R9.2
  Bottom Layer w0.45: R7.2 82.05,82.15 83.1,83.2 83.1,88.9 v1(81.7,90.3)
NetR16_1: R16.1 R17.2 VT3.1 | length 15.4
  Top Layer w0.45: R16.1 v1@112.989,103.989
  Bottom Layer w0.45: VT3.1 108.923,93.473 R17.2 ; v1(113,104.4) v1@113,104.8
  Bottom Layer w0.55: R17.2 110.65,96.95 113,99.3 v1(113,104.4)
NetR18_2: R18.2 VT3.3 | length 8.6
  Bottom Layer w0.45: R18.2@99.112,90.3 101.9,90.3 104,92.4 VT3.3
NetR21_1: R21.1 X3.6 | length 2
  Bottom Layer w0.45: X3.6 60.855,94.145 R21.1
NetR22_1: R22.1 R23.1 VT4.1 | length 10.8
  Top Layer w0.45: VT4.1 VT4.1@88.5,101.45 ; v1@90.1,103.5 v1(90.145,103.545)
  Top Layer w0.55: VT4.1@88.5,101.45 R23.1 v1(90.145,103.545)
  Bottom Layer w0.45: v1(90.145,103.545) 90.145,96.81 R22.1
NetVD1_1: VD1.1 X1.1 | length 2.4
  Top Layer w0.45: VD1.1 VD1.1@37.433,104.267
  Top Layer w0.8: VD1.1@37.433,104.267 X1.1
pads on no net: DD2.2 DD2.9 DD2.10 DD2.11 DD2.12 DD2.13 DD2.14 DD2.19 DD2.20 DD2.22 DD2.23 DD2.24 DD2.26 DD2.27 DD2.28 DD3.2 DD3.3 DD3.5 DD3.6 DD3.7 DD3.8 DD3.11 DD3.12 DD3.13 DD3.14 DD3.15 DD3.16 DD3.23 DD3.24 DD3.25 DD3.27 DD3.28 DD3.34 DD3.35 DD3.36 DD3.37 DD3.38 DD3.40 DD3.41 DD3.42 DD3.43 DD3.44 DD3.47 DD3.48 DD3.49 DD3.50 DD3.51 DD3.66 DD3.67 DD3.68 DD4.2
copper on no net: | length 7
  Top Layer w0.45: 33,92.2 34,92.2 ; 33.5,91.7 33.5,92.7 ; 39.223,107.44 40.223,107.44 ; 39.723,106.94 39.723,107.94 ; 42.672,107.442 43.672,107.442 ; 57.5,73.8 58.5,73.8 ; 58,73.3 58,74.3

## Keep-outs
Keep-Out Layer:
  the board outline again, w0.254

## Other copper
Top Layer:
  rectangle net GND: 109.8,83 112.1,88.5
  rectangle net GND: 100.2,81.7 110.3,89.3
  rectangle net GND: 102.6,90.4 112.1,95.9
  rectangle net GND: 99.2,95.7 112.1,96.6
  rectangle net GND: 98.7,89.2 110.3,92.7
  rectangle net GND: 91,89.2 99.5,96.6
  rectangle net GND: 91,83 94,96.6
  rectangle net GND: 91,75.5 112.1,83
  text "GSM LOCK" at 64.389,105.664 h2.1
  text "V1.0" at 69.215,102.616 h2.1
  text "1" at 88.7,96.2 h1.5
  text "SIM" at 69.977,65.786 h2.1 r90
Bottom Layer:
  text "." at 76.2,86.995 h1.6

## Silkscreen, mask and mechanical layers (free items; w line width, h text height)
Top Overlay:
  circle w0.254: c65,100 r3.75
  circle w0.254: c81,100 r3.75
